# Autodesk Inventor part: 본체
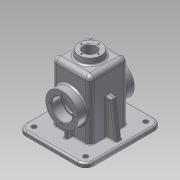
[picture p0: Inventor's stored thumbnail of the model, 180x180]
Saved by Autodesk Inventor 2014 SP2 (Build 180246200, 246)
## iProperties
Created: 2016-08
Part Number: 본체
Material: 알루미늄 6061
Document SubType Name: Modeling
Designer: user
Density: 2.71 g/cm^3
Appearance: 알루미늄 - 평지
Mass: 796.088 g
Surface Area: 911.213 cm^2
Volume: 293.76 cm^3
Author: user
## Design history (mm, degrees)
sketch "스케치1"
  geometry: L1 (-52.5, -60)-(52.5, -60); L2 (52.5, -60)-(52.5, 60); L3 (52.5, 60)-(-52.5, 60); L4 (-52.5, 60)-(-52.5, -60); L5 (-52.5, -60)-(52.5, 60); L6 (52.5, -60)-(-52.5, 60); 1 further point
  constraints: 12 end point, 2 midpoint, 2 parallel, 1 horizontal, 1 perpendicular
  dimensions: "d0" = 105 distance of L3.end L2.end; "d1" = 120 distance of L2.end L1.end
extrude "돌출1" new body sketch "스케치1" distance "d2" = 3; taper "d3" = 0 deg
sketch "스케치2"
  geometry: L1 (-57.5, -65)-(57.5, -65); L2 (57.5, -65)-(57.5, 65); L3 (57.5, 65)-(-57.5, 65); L4 (-57.5, 65)-(-57.5, -65); L5 (-57.5, -65)-(57.5, 65); L6 (57.5, -65)-(-57.5, 65); 1 further point
  constraints: 12 end point, 2 midpoint, 2 parallel, 1 horizontal, 1 perpendicular
  dimensions: "d4" = 115 distance of L3.end L2.end; "d5" = 130 distance of L2.end L1.end
extrude "돌출2" join sketch "스케치2" distance "d6" = 7; taper "d7" = 0 deg
sketch "스케치3"
  geometry: L1 (-32.5, -32.5)-(32.5, -32.5); L2 (32.5, -32.5)-(32.5, 32.5); L3 (32.5, 32.5)-(-32.5, 32.5); L4 (-32.5, 32.5)-(-32.5, -32.5); L5 (-32.5, -32.5)-(32.5, 32.5); L6 (32.5, -32.5)-(-32.5, 32.5); 1 further point
  constraints: 12 end point, 2 midpoint, 2 parallel, 1 horizontal, 1 perpendicular
  dimensions: "d8" = 65 distance of L3.end L2.end; "d9" = 65 distance of L2.end L1.end
extrude "돌출3" join sketch "스케치3" distance "d10" = 100; taper "d11" = 0 deg
sketch "스케치4"
  geometry: L1 (27.5, 27.5)-(-27.5, 27.5); L2 (-27.5, 27.5)-(-27.5, -27.5); L3 (-27.5, -27.5)-(27.5, -27.5); L4 (27.5, -27.5)-(27.5, 27.5); L5 (27.5, 27.5)-(-27.5, -27.5); L6 (-27.5, 27.5)-(27.5, -27.5); 3 further points
  constraints: 12 end point, 3 midpoint, 2 parallel, 1 coincident, 1 horizontal, 1 perpendicular
  dimensions: "d12" = 55 distance of L3.end L2.end; "d13" = 55 distance of L2.end L1.end
extrude "돌출4" cut sketch "스케치4" distance "d14" = 105; taper "d15" = 0 deg
sketch "스케치5"
  geometry: C1 r 27.5 at (32.5, 45); 1 further point
  constraints: 1 centre point, 1 vertical alignment
  dimensions: "d16" = 55 diameter of C1; "d17" = 55 distance of point (32.5, -10) C1.centre
extrude "돌출5" join sketch "스케치5" distance "d18" = 15; taper "d19" = 0 deg
sketch "스케치6"
  geometry: C1 r 27.5 at (32.5, -45); 1 further point
  constraints: 1 centre point, 1 vertical alignment
  dimensions: "d20" = 55 diameter of C1; "d21" = 55 distance of C1.centre point (32.5, 10)
extrude "돌출6" join sketch "스케치6" distance "d22" = 15; taper "d23" = 0 deg
sketch "스케치7"
  geometry: C1 r 17.5 at (0, 0); 1 further point
  constraints: 1 centre point, 1 vertical alignment
  dimensions: "d24" = 35 diameter of C1; "d25" = 55 distance of point (0, -55) C1.centre
extrude "돌출7" cut sketch "스케치7" distance "d26" = 17; taper "d27" = 0 deg
sketch "스케치8"
  geometry: L1 (27.5, 55)-(-27.5, 55) reference; C1 r 17.5 at (0, 0); 2 further points
  constraints: 1 centre point, 1 midpoint, 1 vertical alignment
  dimensions: "d28" = 35 diameter of C1; "d29" = 55 distance of C1.centre point (0, 55)
extrude "돌출8" cut sketch "스케치8" distance "d30" = 17; taper "d31" = 0 deg
sketch "스케치9"
  geometry: C1 r 15 at (0, 0); 1 further point
  constraints: 1 centre point, 1 vertical alignment
  dimensions: "d32" = 30 diameter of C1; "d33" = 55 distance of point (0, 55) C1.centre
extrude "돌출9" cut sketch "스케치9" stored distance "d34" = 17; taper "d35" = 0 deg
sketch "스케치10"
  geometry: C1 r 20 at (0, 0); 1 further point
  constraints: 1 centre point, 1 coincident
  dimensions: "d36" = 40 diameter of C1
extrude "돌출10" join sketch "스케치10" distance "d37" = 10; taper "d38" = -7 deg
sketch "스케치11"
  geometry: C1 r 10.5 at (0, 0); 1 further point
  constraints: 1 centre point, 1 coincident
  dimensions: "d39" = 21 diameter of C1
extrude "돌출11" cut sketch "스케치11" stored distance "d40" = 10; taper "d41" = 0 deg
fillet "모깎기1" dims "d42" = 8
fillet "모깎기2" dims "d43" = 8
sketch "스케치12" dims "d44" = 42
  geometry: 3 further points
  constraints: 3 vertical alignment, 2 other
  dimensions: "d45" = 55 distance of point (0, -55) point (0, 0)
hole "구멍1" sketch "스케치12" at (0, 21) diameter "d46" = 3.242; stored, may be unused: countersink angle "d50" = 90 deg, drill point angle "d52" = 118 deg; dims "d47" = 8, "d48" = 4, "d49" = 2, "d51" = 10
sketch "스케치13" dims "d56" = 42
  geometry: 3 further points
  constraints: 3 vertical alignment, 2 other
  dimensions: "d57" = 55 distance of point (0, 0) point (0, 55)
hole "구멍2" sketch "스케치13" at (0, -21) diameter "d58" = 3.242; stored, may be unused: countersink angle "d62" = 90 deg, drill point angle "d64" = 118 deg; dims "d59" = 8, "d60" = 4, "d61" = 2, "d63" = 10
sketch "스케치14"
  geometry: L1 (-57.5, -65)-(57.5, -65) reference; L2 (57.5, -65)-(57.5, 65) reference; C1 r 4 at (43.5, -51); 1 further point
  constraints: 1 centre point
  dimensions: "d68" = 8 diameter of C1; "d69" = 14 distance from line of L1 C1.centre; "d70" = 14 distance from line of C1.centre L2
extrude "돌출12" cut sketch "스케치14" stored distance "d71" = 10; taper "d72" = 0 deg
sketch "스케치15"
  geometry: L1 (27.5, 27.5)-(-27.5, 27.5) reference; L2 (3, 27.5)-(3, 42.5); L3 (3, 42.5)-(-3, 42.5); L4 (-3, 42.5)-(-3, 27.5); 2 further points
  constraints: 6 end point, 2 parallel, 2 point on line, 1 midpoint, 1 perpendicular, 1 vertical alignment
  dimensions: "d79" = 6 distance of L2.end L3.end; "d80" = 15 distance between parallel lines of L1 L3
extrude "돌출13" join sketch "스케치15" stored distance "d81" = 10; taper "d82" = 0 deg
sketch "스케치16"
  geometry: L1 (39.5, 10)-(47.5, 10) reference; L2 (49.5, 10)-(41.068, 70); L3 (57.5, 3)-(57.5, 10) reference; L4 (41.068, 70)-(32.5, 70); L5 (32.5, 102)-(32.5, 10) reference; L6 (52.5, 0)-(-52.5, 0) reference; 1 further point
  constraints: 4 end point, 2 point on line, 1 perpendicular
  dimensions: "d83" = 8 deg angle of L3 L2; "d84" = 8 distance from line of L3 L2.start; "d113" = 70 distance between parallel lines of L6 L4
feature "리브1" sketch "스케치16" dims "d86" = 1, "d87" = 10, "d88" = 0, "d89" = 0, "d90" = 1, "d91" = 1
fillet "모깎기3" dims "d92" = 0.3
fillet "모깎기4" dims "d93" = 0.3
fillet "모깎기5" dims "d94" = 9
fillet "모깎기6" dims "d95" = 14
fillet "모깎기7" dims "d96" = 3
fillet "모깎기8" dims "d97" = 3
fillet "모깎기9" dims "d98" = 3
fillet "모깎기10" dims "d99" = 3
fillet "모깎기11" dims "d100" = 3
fillet "모깎기12" dims "d101" = 1
fillet "모깎기13" dims "d102" = 3
fillet "모깎기14" dims "d103" = 3
fillet "모깎기15" dims "d104" = 3
fillet "모깎기16" dims "d105" = 3
fillet "모깎기17" dims "d106" = 3
chamfer "모따기1" distance "d107" = 1; stored, may be unused: second distance "d108" = 2, angle "d109" = 45 deg
chamfer "모따기2" distance "d110" = 1; stored, may be unused: second distance "d111" = 2, angle "d112" = 45 deg
sketch "스케치17" dims "d114" = 29
  geometry: 3 further points
  constraints: 2 vertical alignment, 1 coincident, 2 other
hole "구멍3" sketch "스케치17" at (0, 14.5) diameter "d115" = 2.459; stored, may be unused: countersink angle "d119" = 90 deg, drill point angle "d121" = 118 deg; dims "d116" = 7, "d117" = 4, "d118" = 2, "d120" = 9
chamfer "모따기3" distance "d125" = 1; stored, may be unused: second distance "d126" = 2, angle "d127" = 45 deg
node "작업 평면1"
sketch "스케치18"
  geometry: L1 (43.272, -18)-(5.728, -18) reference; L2 (57, 0)-(57, 91) reference; 2 further points
  constraints: 1 vertical alignment, 1 other
  dimensions: "d130" = 32.5 distance from line of L2 point (24.5, 8) (derived); "d133" = 26 distance from line of L1 point (24.5, 8)
feature "엠보싱1" sketch "스케치18" dims "d131" = 0.5, "d132" = 0
fillet "모깎기18" dims "d134" = 3
fillet "모깎기19" dims "d135" = 3
node "솔리드1"
pattern_circular "원형 패턴1" dims angle "d54" = 360 deg
pattern_circular "원형 패턴2" dims angle "d66" = 360 deg
pattern_linear "직사각형 패턴1" dims "d75" = 87, "d78" = 102
mirror "대칭1"
mirror "대칭2"
pattern_circular "원형 패턴3" dims angle "d123" = 360 deg
other parameters: "d128" = 37.5
